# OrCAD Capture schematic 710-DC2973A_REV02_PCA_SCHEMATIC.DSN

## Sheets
1 PAGE 2: size Custom; note: PRIMARY BATTERY SOH MONITOR WITH PRECISION COULOMB COUNTER / PRECISION COULOMB COUNTER
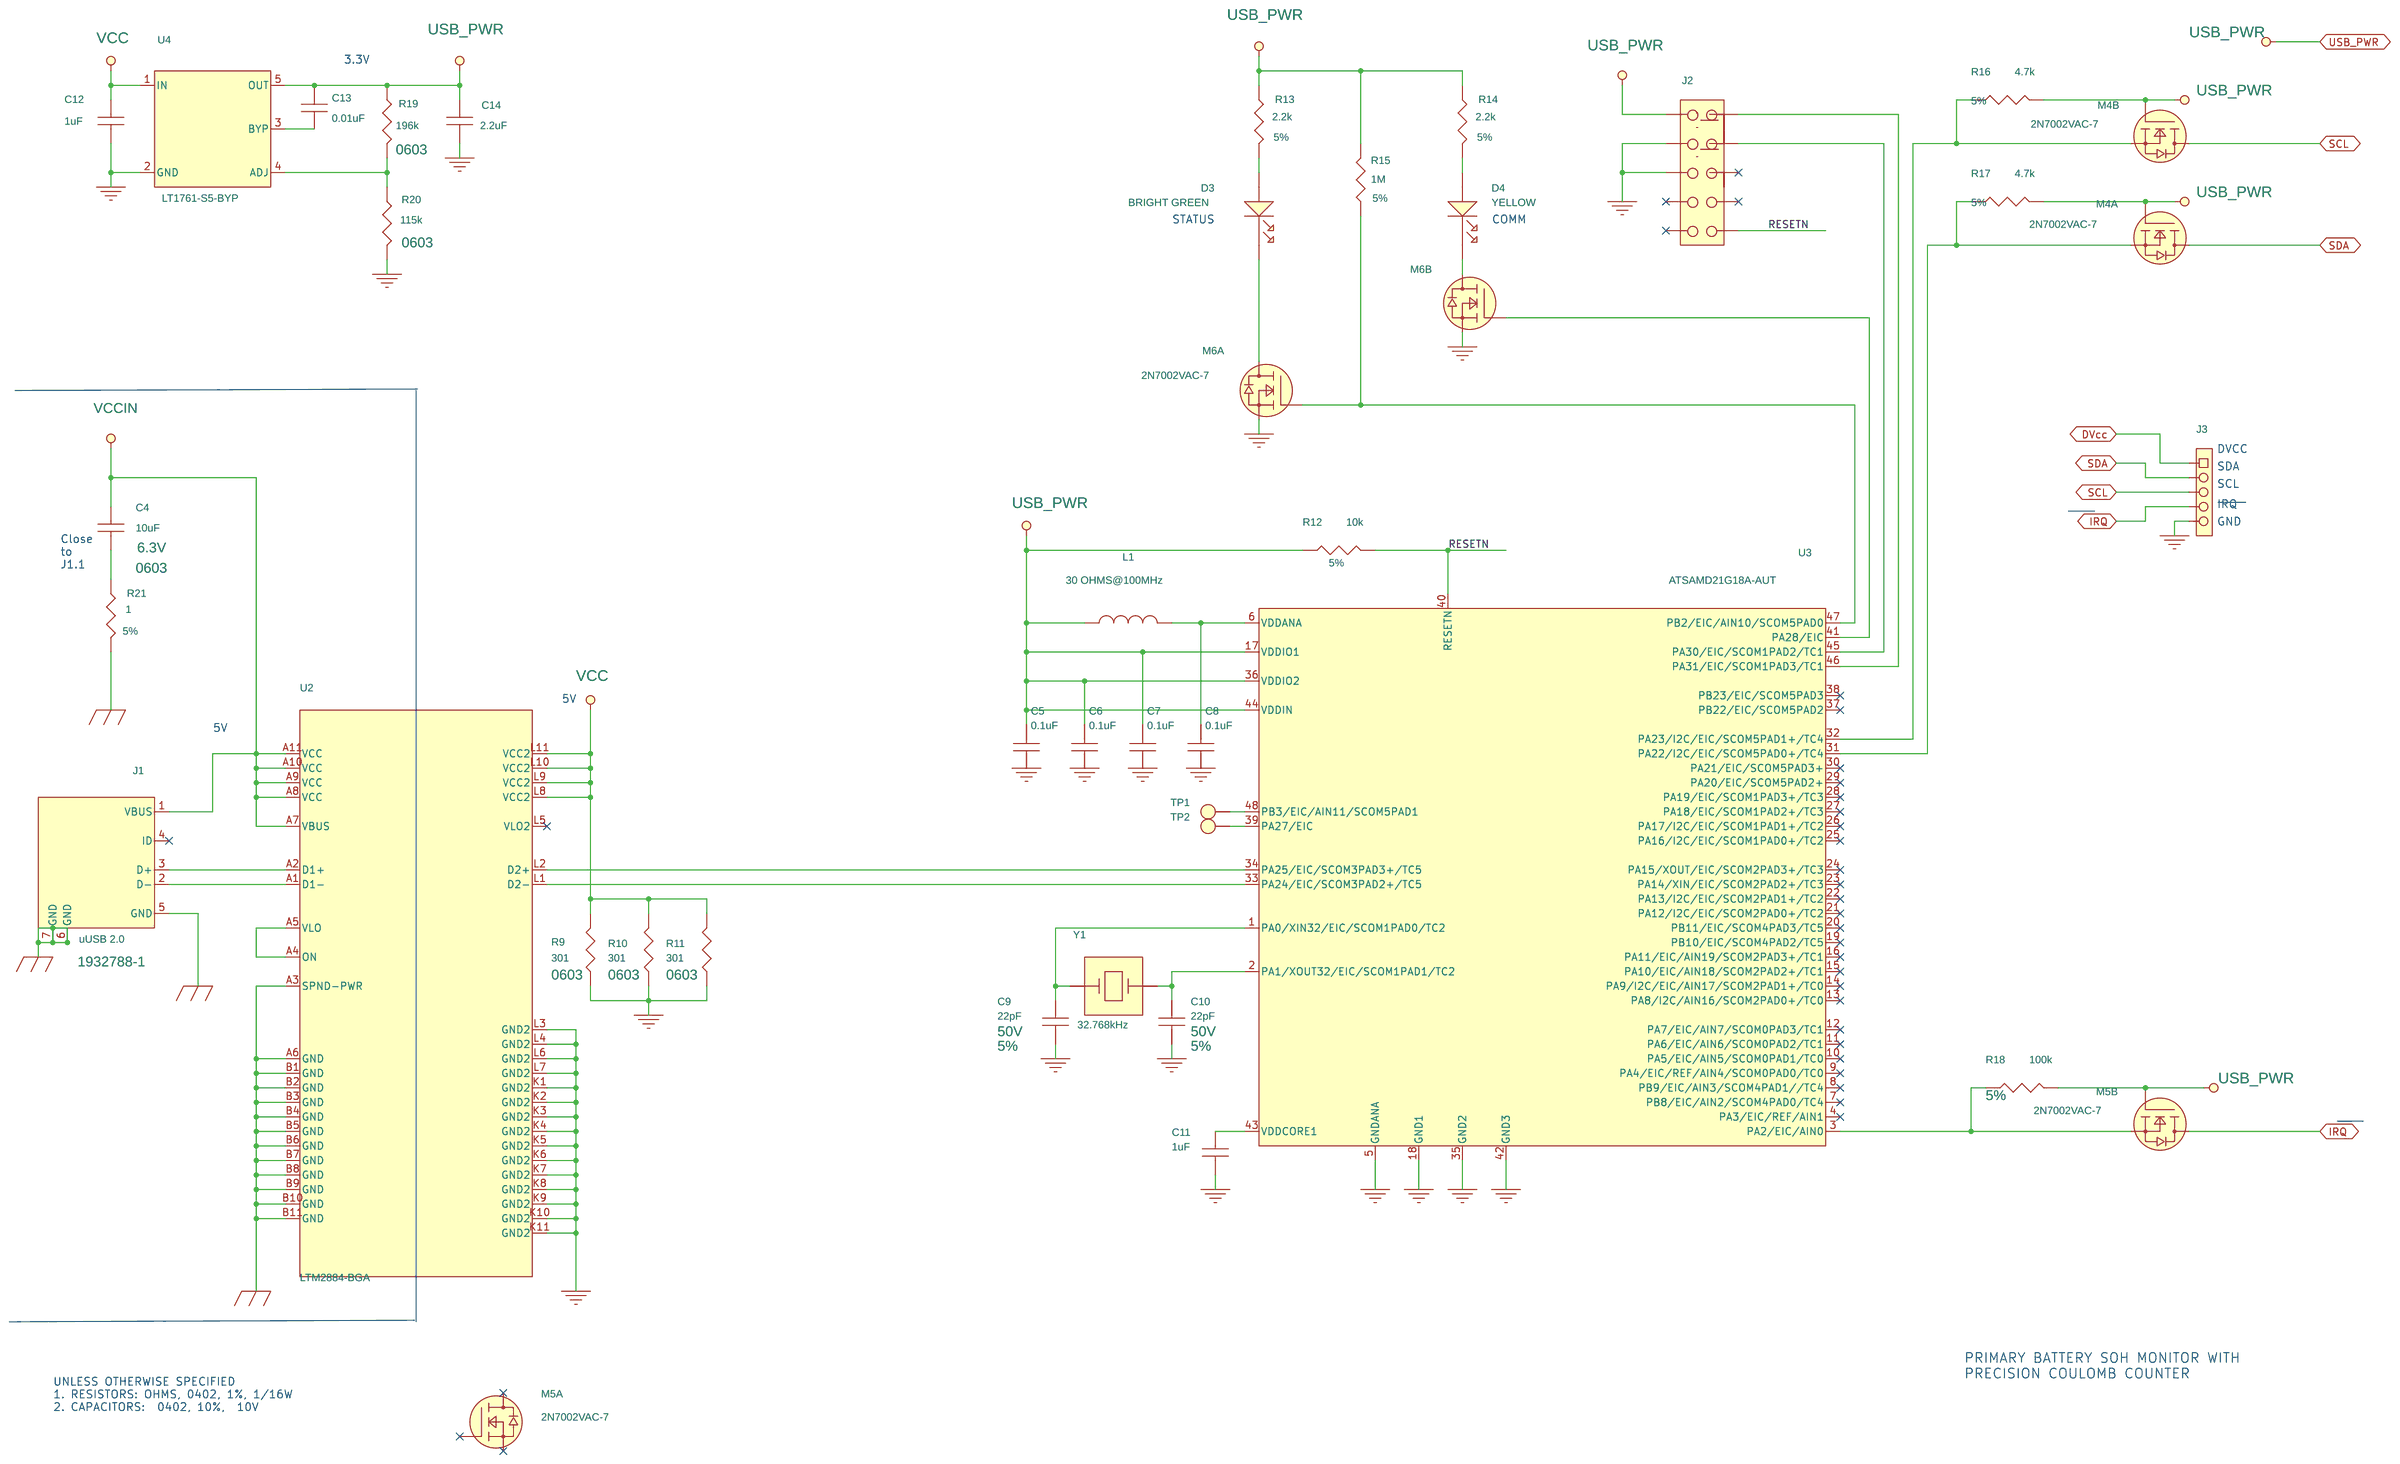
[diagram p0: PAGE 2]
2 PAGE 1: size B
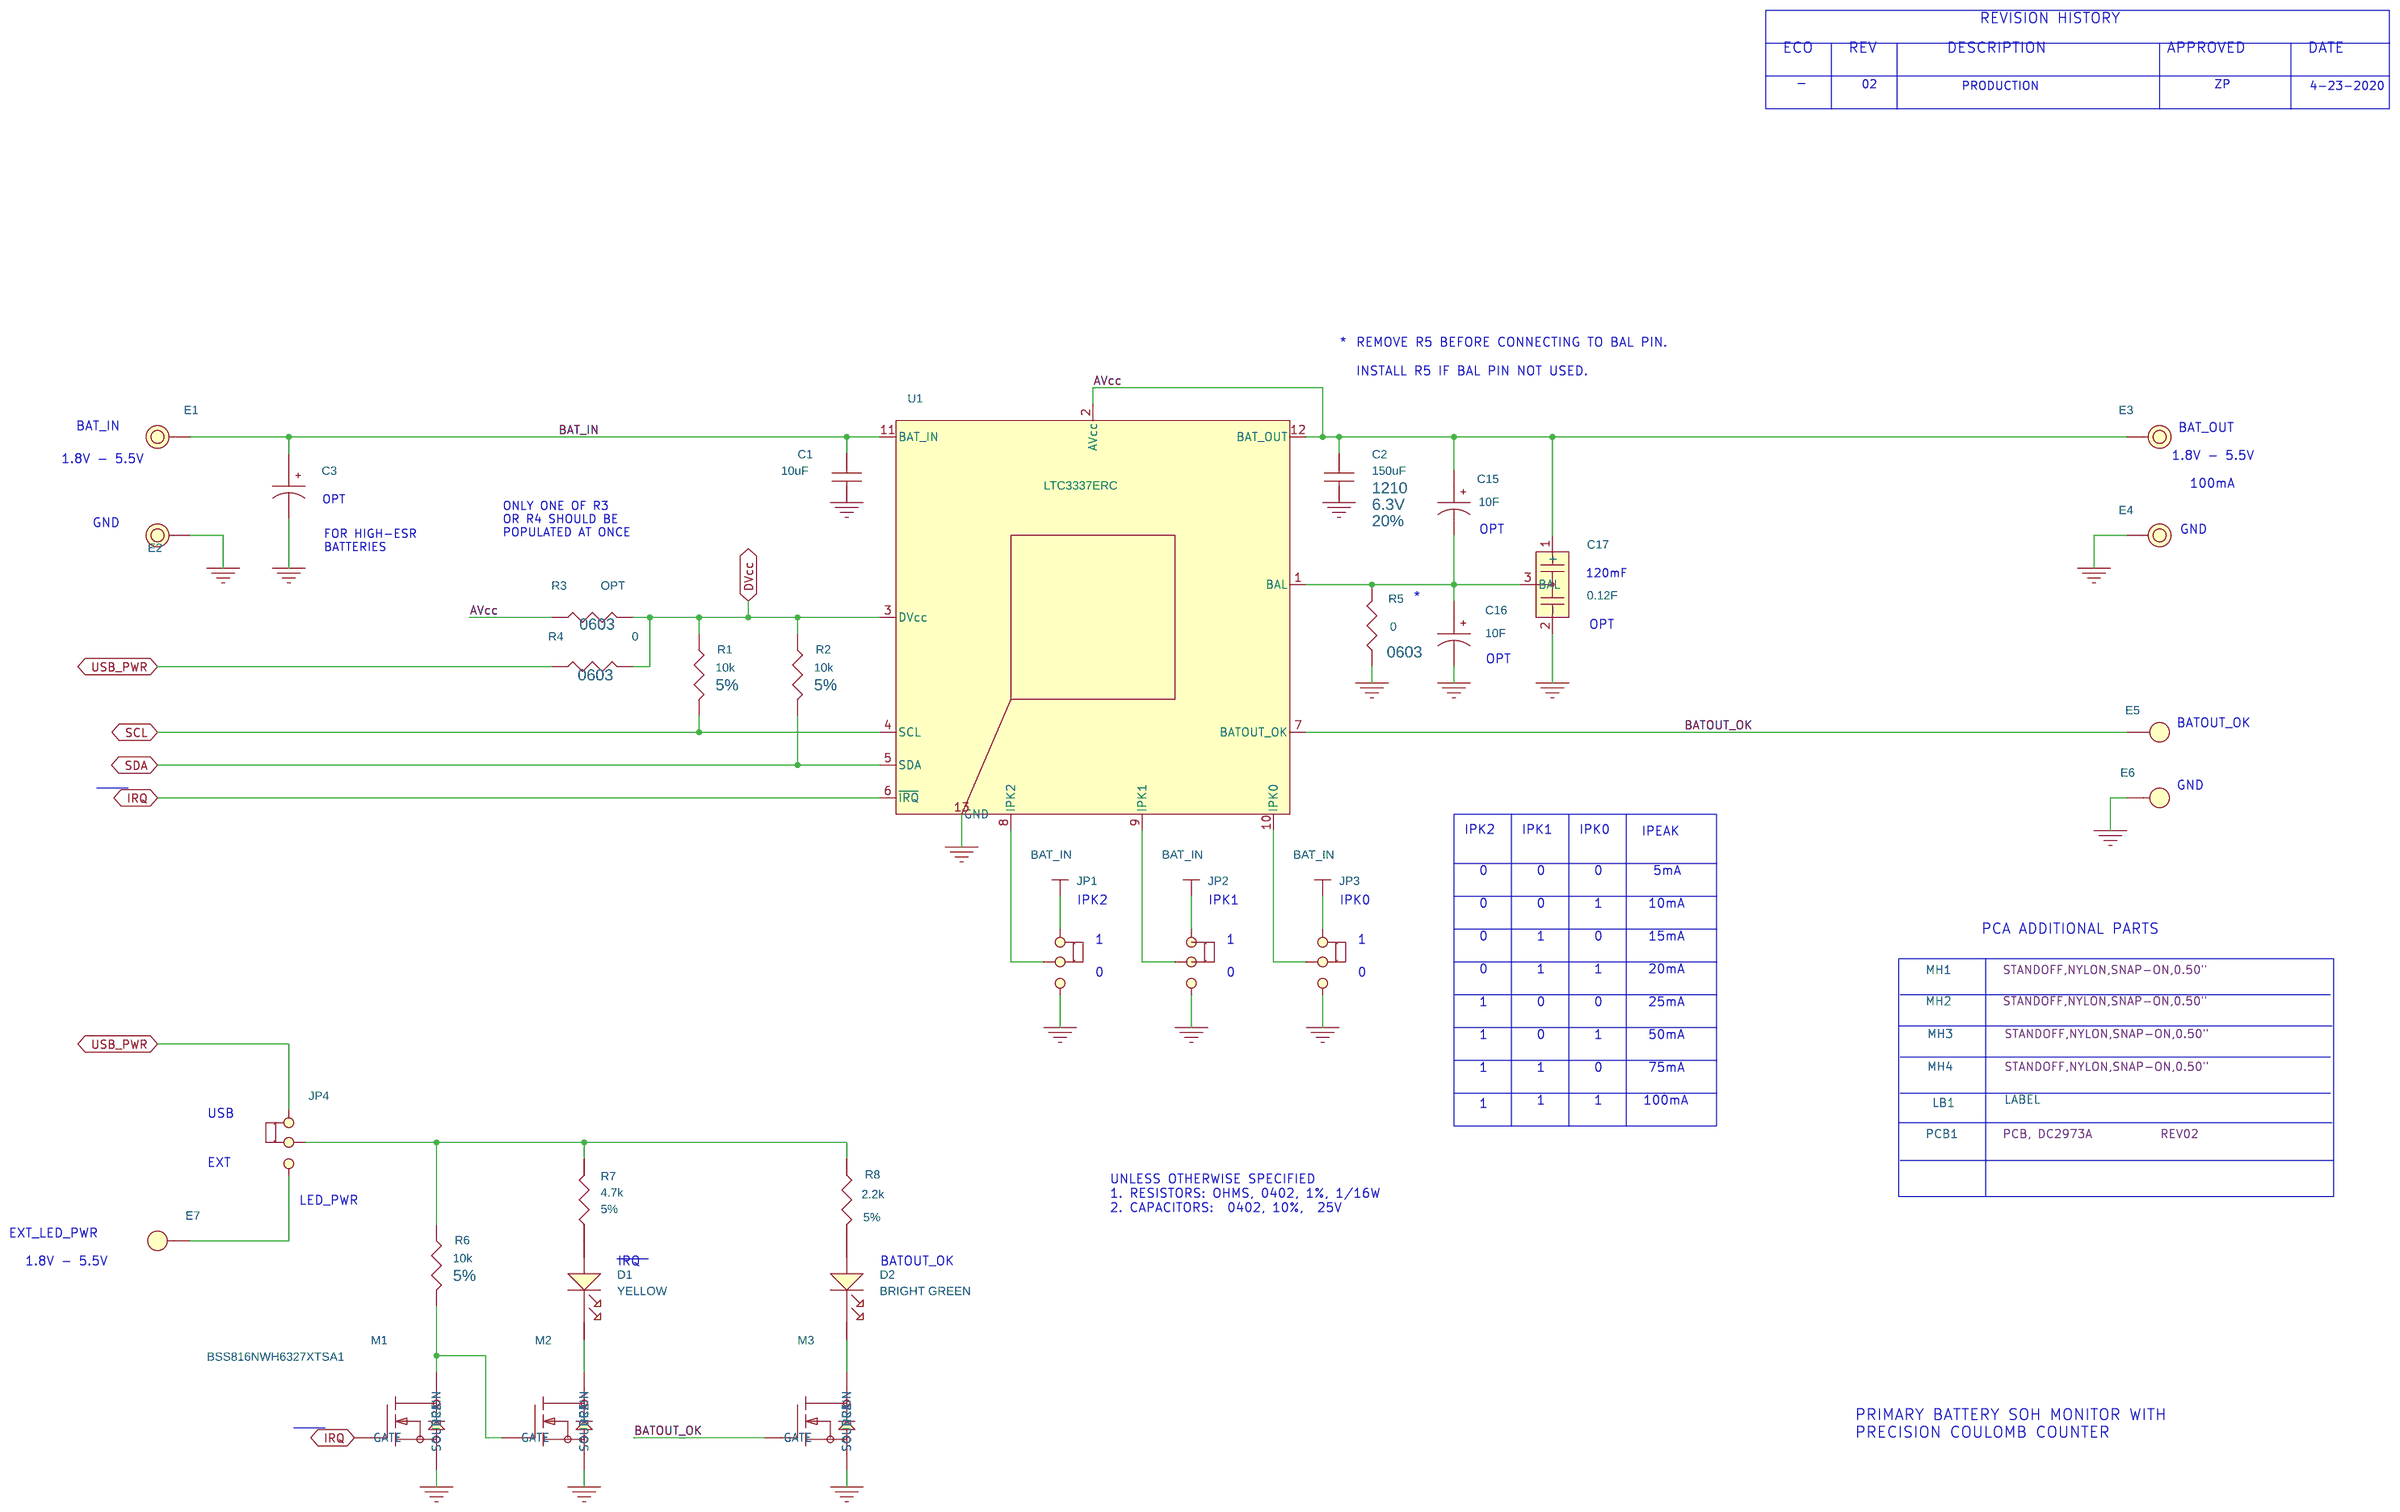
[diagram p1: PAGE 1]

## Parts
sheet PAGE 1
C1  10uF  [CC0603N]
C2  150uF  [CC1210N]
C3  180uF  [PANASONIC_SVPF_8X11.9]
C15  10F  [CAP-ESHSR-0010-0050C0-002R7]
C16  10F  [CAP-ESHSR-0010-0050C0-002R7]
C17  0.12F  [CAP-XX_HA202F]
D1  YELLOW  [LED_0603]
D2  BRIGHT GREEN  [LED_0603]
E1  TEST POINT  [MILLMAX2501]
E2  TEST POINT  [MILLMAX2501]
E3  TEST POINT  [MILLMAX2501]
E4  TEST POINT  [MILLMAX2501]
E5  TEST POINT  [MILLMAX2308]
E6  TEST POINT  [MILLMAX2308]
E7  TEST POINT  [MILLMAX2308]
JP1  HDR  [HD1X3-079]
JP2  HDR  [HD1X3-079]
JP3  HDR  [HD1X3-079]
JP4  HDR  [HD1X3-079]
LB1  LABEL  [895-0154_REV01]
M1  BSS816NWH6327XTSA1  [SOT323-3N]
M2  BSS816NWH6327XTSA1  [SOT323-3N]
M3  BSS816NWH6327XTSA1  [SOT323-3N]
MH1  STANDOFF  [KEYSTONE_8829-8834]
MH2  STANDOFF  [KEYSTONE_8829-8834]
MH3  STANDOFF  [KEYSTONE_8829-8834]
MH4  STANDOFF  [KEYSTONE_8829-8834]
PCB1  PCB, DC2973A
R1  10k  [CR0402N]
R2  10k  [CR0402N]
R3  OPT  [CR0603N]
R4  0  [CR0603N]
R5  0  [CR0603N]
R6  10k  [CR0402N]
R7  4.7k  [CR0402N]
R8  2.2k  [CR0402N]
U1  LTC3337ERC  [LTC-GQFN-12-1784]
XJP1  SHUNT
XJP2  SHUNT
XJP3  SHUNT
XJP4  SHUNT
sheet PAGE 2
C4  10uF  [CC0603N]
C5  0.1uF  [CC0402N]
C6  0.1uF  [CC0402N]
C7  0.1uF  [CC0402N]
C8  0.1uF  [CC0402N]
C9  22pF  [CC0402N]
C10  22pF  [CC0402N]
C11  1uF  [CC0402N]
C12  1uF  [CC0402N]
C13  0.01uF  [CC0402N]
C14  2.2uF  [CC0402N]
D3  BRIGHT GREEN  [LED_0603]
D4  YELLOW  [LED_0603]
J1  uUSB 2.0  [TE-1932788-1]
J2  HDR  [WURTH-62201021121]
J3  HDR  [HD1X5-100]
L1  30 OHMS@100MHz  [IND0805N]
M4  2N7002VAC-7  [SOT563-6N]  (sections A,B)
M5  2N7002VAC-7  [SOT563-6N]  (sections A,B)
M6  2N7002VAC-7  [SOT563-6N]  (sections A,B)
R9  301  [CR0603N]
R10  301  [CR0603N]
R11  301  [CR0603N]
R12  10k  [CR0402N]
R13  2.2k  [CR0402N]
R14  2.2k  [CR0402N]
R15  1M  [CR0402N]
R16  4.7k  [CR0402N]
R17  4.7k  [CR0402N]
R18  100k  [CR0402N]
R19  196k  [CR0603N]
R20  115k  [CR0603N]
R21  1  [CR0402N]
TP1  TEST PAD  [PADSTYLE1]
TP2  TEST PAD  [PADSTYLE1]
U2  LTM2884-BGA  [LTC-BGA-44-1881]
U3  ATSAMD21G18A-AUT  [MICROCHIP-TQFP48-NO_TAB]
U4  LT1761-S5-BYP  [LTC-S5-5-1635]
Y1  32.768kHz  [ECX-31B]

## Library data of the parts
C1 = CAP: CAP.,10uF,X5R,10V,10%,0603; CLASS: DISCRETE; Dielectric Type: X5R; FPLIST: CC0603N,CC0603L,CC0603M; Inventory Qty: 23058; Manufacturer: AVX; Manufacturer PN: 0603ZD106KAT2A; PART_NUMBER: 150-0576; Package Size: 0603; Rated Voltage: 10V; Tolerance: 10%
C2 = CAP: CAP.,150uF,X5R,6.3V,20%,1210; CLASS: DISCRETE; Dielectric Type: X5R; FPLIST: CC1210N,CC1210L,CC1210M; Inventory Qty: 522; Manufacturer: SAMSUNG; Manufacturer PN: CL32A157MQVNNNE; PART_NUMBER: 150-3513; Package Size: 1210; Rated Voltage: 6.3V; Tolerance: 20%
C3 = CAP_P_ALT: CAP.,180uF,ALUM POLY,OS-CON,25V,20%,8x11.9mm,SMD,RADIAL,E12; CLASS: DISCRETE; Dielectric Type: ALUM POLY,OS-CON; Inventory Qty: 4546; Manufacturer: PANASONIC; Manufacturer PN: 25SVPF180M; PART_NUMBER: 150-2329; Package Size: 8x11.9mm,SMD,RADIAL,E12; Rated Voltage: 25V; Tolerance: 20%; UserField01: 16mOhms, 4.65A
C15 C16 = CAP_P_ALT: CAP.,10F,ULTRA,2.7V,-10/+20%,RADIAL,THT; CLASS: DISCRETE; Dielectric Type: ULTRA; Inventory Qty: 472; Manufacturer: NESSCAP CO. LTD.; Manufacturer PN: BCAP0010 P270 S01; PART_NUMBER: 150-0245; Package Size: RADIAL,THT; Rated Voltage: 2.7V; Tolerance: -10/+20%
C17 = CAP-XX-HA202F: CAP.,0.12F,SUPERCAP,HIGH TEMP,5.5V,20%,20mmX18mmX2.5mm,SMD,DUAL CELL; CLASS: DISCRETE; Dielectric Type: SUPERCAP,HIGH TEMP; Inventory Qty: 0; Manufacturer: CAP-XX; Manufacturer PN: HA202F; PART_NUMBER: 150-1825; Package Size: 20mmX18mmX2.5mm,SMD; Package Type: Surface Mount; Rated Voltage: 5.5V; Tolerance: 20%
D1 D4 = LED_ALT: LED,YELLOW,WATERCLEAR,0603; CLASS: DISCRETE; FPLIST: LED_0603N,LED_0603L,LED_0603M; Inventory Qty: 342; Manufacturer: WURTH ELEKTRONIK; Manufacturer PN: 150060YS75000; PART_NUMBER: 270-0136; Package Size: 0603 (1608 Metric); Package Type: 0603
D2 D3 = LED_ALT: LED,BRIGHT GREEN,WATERCLEAR,0603; CLASS: DISCRETE; FPLIST: LED_0603N,LED_0603L,LED_0603M; Inventory Qty: 1970; Manufacturer: WURTH ELEKTRONIK; Manufacturer PN: 150060VS75000; PART_NUMBER: 270-0072; Package Size: 0603 (1608 Metric); Package Type: 0603
E1-E4 = TESTPOINT_.219_MILL-MAX_2501: TEST POINT,TURRET,0.094" MTG. HOLE,PCB 0.062" THK; CLASS: IO; Inventory Qty: 609555; Manufacturer: MILL-MAX; Manufacturer PN: 2501-2-00-80-00-00-07-0; PART_NUMBER: 260-0003
E5-E7 = TEST_POINT_.156_MILL-MAX_2308: TEST POINT,TURRET,0.064" MTG. HOLE,PCB 0.062" THK; CLASS: IO; Inventory Qty: 907628; Manufacturer: MILL-MAX; Manufacturer PN: 2308-2-00-80-00-00-07-0; PART_NUMBER: 260-0004
JP1-JP4 = HDR3X1_A: CONN.,HDR,MALE,1x3,2mm,VERT,ST,THT,10u" Au; CLASS: IO; Inventory Qty: 44806; Manufacturer: SAMTEC; Manufacturer PN: TMM-103-02-L-S; PART_NUMBER: 250-0422
LB1 = BLANK_LABEL: LABEL SPEC, DEMO BOARD SERIAL NUMBER; Inventory Qty: 0; Manufacturer: BRADY; Manufacturer PN: THT-96-717-10; PART_NUMBER: 895-0154
M1-M3 = NMOS_SOT: XSTR.,MOSFET, N-CH,20V,1.4A,SOT-323,AEC-Q200; CLASS: DISCRETE; FPLIST: SOT323-3N,SOT323-3L,SOT323-3M; Inventory Qty: 5950; Manufacturer: INFINEON; PART_NUMBER: 240-0375; Package Size: SC-70, SOT-323; Package Type: SOT-323; Polarity: N-Channel; Rated Voltage: 20V
MH1-MH4 = BLANK_MECHANICAL_PART: STANDOFF,NYLON,SNAP-ON,0.50"; CLASS: DISCRETE; Inventory Qty: 197874; Manufacturer: KEYSTONE; Manufacturer PN: 8833; PART_NUMBER: 763-0007
PCB1 = BLANK_PCB_PART: BOM Notes: REV02; CLASS: DISCRETE; Inventory Qty: 0; Manufacturer: ADI APPROVED SUPPLIER; Manufacturer PN: 600-DC2973A; PART_NUMBER: 600-DC2973A
R1 R2 R6 = RES: RES.,10k OHMS,5%,1/16W,0402,AEC-Q200; CLASS: DISCRETE; FPLIST: CR0402N,CR0402L,CR0402M; Inventory Qty: 69667; Manufacturer: NIC; Manufacturer PN: NRC04J103TRF; PART_NUMBER: 100-0214; Package Size: 0402; Rated Power: 1/16W; Temperature Coefficient: 200ppm; Tolerance: 5%
R3 = RES: RES., OPTION, 0603; CLASS: DISCRETE; FPLIST: CR0603N,CR0603L,CR0603M; PART_NUMBER: 100-2374; Package Size: 0603
R4 R5 = RES: RES.,0 OHM,1%,0603,AEC-Q200; CLASS: DISCRETE; FPLIST: CR0603N,CR0603L,CR0603M; Inventory Qty: 34533; Manufacturer: KOA SPEER; Manufacturer PN: RK73Z1JTTDD; PART_NUMBER: 100-0596; Package Size: 0603; Tolerance: 1%
R7 R16 R17 = RES: RES.,4.7k OHMS,5%,1/16W,0402,AEC-Q200; CLASS: DISCRETE; FPLIST: CR0402N,CR0402L,CR0402M; Inventory Qty: 31964; Manufacturer: NIC; Manufacturer PN: NRC04J472TRF; PART_NUMBER: 100-0216; Package Size: 0402; Rated Power: 1/16W; Temperature Coefficient: 200ppm; Tolerance: 5%
R8 R13 R14 = RES: RES.,2.2k OHMS,5%,1/16W,0402,AEC-Q200; CLASS: DISCRETE; FPLIST: CR0402N,CR0402L,CR0402M; Inventory Qty: 57911; Manufacturer: VISHAY; Manufacturer PN: CRCW04022K20JNED; PART_NUMBER: 100-0324; Package Size: 0402; Rated Power: 1/16W; Temperature Coefficient: 200ppm; Tolerance: 5%
U1 = LTC3337-GQFN: Primary Battery SOH Monitor w/ Precision Coulomb Counter,GQFN-12; CLASS: IC; Inventory Qty: 0; Manufacturer: ANALOG DEVICES; Manufacturer PN: LTC3337ERC#PBF; PART_NUMBER: LTC3337ERC#PBF; Package Size: 12-GQFN; Package Type: GQFN-12
XJP1-XJP4 = CONN_SHUNT_2_POS_2mm: CONN.,SHUNT,FEMALE,2 POS,2mm; CLASS: IO; Inventory Qty: 67675; Manufacturer: Wurth Elektronik; Manufacturer PN: 60800213421; PART_NUMBER: 250-0485
C4 = CAP: CAP.,10uF,X5R,6.3V,20%,0603; CLASS: DISCRETE; Dielectric Type: X5R; Inventory Qty: 62711; Manufacturer: MURATA; Manufacturer PN: GRM188R60J106ME47D; PART_NUMBER: 150-3401; Package Size: 0603; Package Type: SMD; Rated Voltage: 6.3V; Tolerance: 20%
C5-C8 = CAP: CAP.,0.1uF,X5R,10V,20%,0402; CLASS: DISCRETE; Dielectric Type: X5R; Inventory Qty: 3880; Manufacturer: WURTH ELEKTRONIK; Manufacturer PN: 885012105010; PART_NUMBER: 150-2539; Package Size: 0402; Package Type: SMD; Rated Voltage: 10V; SIGNAL_MODEL: DEFAULT_CAPACITOR_100000pF_1_2; Temperature Coefficient: X5R; Tolerance: 20%
C9 C10 = CAP: CAP.,22pF,NP0,50V,5%,0402; CLASS: DISCRETE; Dielectric Type: NP0; Inventory Qty: 1440; Manufacturer: WURTH ELEKTRONIK; Manufacturer PN: 885012005057; PART_NUMBER: 150-2540; Package Size: 0402; Package Type: SMD; Rated Voltage: 50V; SIGNAL_MODEL: DEFAULT_CAPACITOR_22.000000pF_1_2; Temperature Coefficient: C0G, NP0; Tolerance: 5%
C11 C12 = CAP: CAP.,1uF,BJ,10V,20%,0402; CLASS: DISCRETE; Dielectric Type: BJ; FPLIST: CC0402N, CC0402M,CC0402L; Inventory Qty: 12000; Manufacturer: TDK; Manufacturer PN: CGB2A1JB1A105M033BC; PART_NUMBER: 150-2558; Package Size: 0402; Package Type: Surface Mount, MLCC; Rated Voltage: 10V; SIGNAL_MODEL: DEFAULT_CAPACITOR_1e+06pF_1_2; Temperature Coefficient: JB; Tolerance: 20%
C13 = CAP: CAP.,0.01uF,X7R,25V,10%,0402; CLASS: DISCRETE; Dielectric Type: X7R; Inventory Qty: 1470; Manufacturer: WURTH ELEKTRONIK; Manufacturer PN: 885012205050; PART_NUMBER: 150-2542; Package Size: 0402; Package Type: SMD; Rated Voltage: 25V; SIGNAL_MODEL: DEFAULT_CAPACITOR_10000pF_1_2; Temperature Coefficient: X7R; Tolerance: 10%
C14 = CAP: CAP.,2.2uF,X5R,10V,20%,0402; CLASS: DISCRETE; Dielectric Type: X5R; Inventory Qty: 1970; Manufacturer: WURTH ELEKTRONIK; Manufacturer PN: 885012105013; PART_NUMBER: 150-2543; Package Size: 0402; Package Type: SMD; Rated Voltage: 10V; SIGNAL_MODEL: DEFAULT_CAPACITOR_2.2e+06pF_1_2; Temperature Coefficient: X5R; Tolerance: 20%
J1 = MICRO_USB_2.0: CONN.,uUSB 2.0,RCPT.,5-PIN,1PORT,REVERSE MOUNT,R/A HORZ.,TYPE B, FLANGELESS; CLASS: IO; Inventory Qty: 3957; Manufacturer: TE CONNECTIVITY; Manufacturer PN: 1932788-1; PART_NUMBER: 250-0536
J2 = HEADER_2X5_.100: CONN.,HDR,MALE,2x5,1.27mm,VERT,ST,THT; CLASS: IO; Inventory Qty: 6170; Manufacturer: WURTH ELEKTRONIK; Manufacturer PN: 62201021121; PART_NUMBER: 250-0763
J3 = HEADER_1X5: CONN.,HDR,MALE,1x5,2.54mm,VERT,ST,THT; CLASS: IO; Inventory Qty: 10760; Manufacturer: SAMTEC; Manufacturer PN: TSW-105-07-L-S; PART_NUMBER: 250-0599; Package Size: 0.230" (5.84mm)
L1 = FERRITEBEAD: IND.,30 OHMS@100MHz,BEAD,10%,6A,10mOHMS,0805,1LN; CLASS: DISCRETE; Inventory Qty: 11475; Manufacturer: TDK; Manufacturer PN: MPZ2012S300AT000; PART_NUMBER: 200-0237; Package Size: 0805; Tolerance: 10%
M4-M6 = 2N7002VAC-7: XSTR.,MOSFET,DUAL,N-CH,280mA,SOT-563; CLASS: DISCRETE; Inventory Qty: 8986; Manufacturer: DIODES INC.; PART_NUMBER: 240-0199; Package Size: SOT-563, SOT-666; Package Type: SOT-563; Polarity: 2 N-Channel (Dual); Rated Power: 150mW; Rated Voltage: 60V
R9-R11 = RES: RES.,301 OHMS,1%,1/10W,0603,AEC-Q200; CLASS: DISCRETE; Inventory Qty: 38848; Manufacturer: PANASONIC; Manufacturer PN: ERJ3EKF3010V; PART_NUMBER: 100-0434; Package Size: 0603; Rated Power: 1/10W; Temperature Coefficient: 100ppm; Tolerance: 1%
R12 = RES: RES.,10k OHMS,5%,1/16W,0402; CLASS: DISCRETE; FPLIST: CR0402N,CR0402L,CR0402M; Inventory Qty: 77544; Manufacturer: SAMSUNG; Manufacturer PN: RC1005J103CS; PART_NUMBER: 100-0023; Package Size: 0402; Rated Power: 1/16W; SIGNAL_MODEL: DEFAULT_RESISTOR_10000OHM_1_2; Temperature Coefficient: +/-100ppm; Tolerance: 5%
R15 = RES: RES.,1M OHM,5%,1/16W,0402,AEC-Q200; CLASS: DISCRETE; FPLIST: CR0402N,CR0402L,CR0402M; Inventory Qty: 26140; Manufacturer: VISHAY; Manufacturer PN: CRCW04021M00JNED; PART_NUMBER: 100-0321; Package Size: 0402; Rated Power: 1/16W; SIGNAL_MODEL: DEFAULT_RESISTOR_0.001OHM_1_2; Temperature Coefficient: 200ppm; Tolerance: 5%
R18 = RES: RES.,100k OHMS,5%,1/16W,0402,AEC-Q200; CLASS: DISCRETE; FPLIST: CR0402N,CR0402L,CR0402M; Inventory Qty: 0; Manufacturer: ROHM; Manufacturer PN: MCR01MZPJ104; PART_NUMBER: 100-0192; Package Size: 0402; Rated Power: 1/16W; Temperature Coefficient: 200ppm/C; Tolerance: 5%
R19 = RES: RES.,196k OHMS,1%,1/10W,0603; CLASS: DISCRETE; FPLIST: CR0603N,CR0603L,CR0603M; Inventory Qty: 23006; Manufacturer: VISHAY; Manufacturer PN: CRCW0603196KFKEA; PART_NUMBER: 100-2660; Package Size: 0603; Rated Power: 1/10W; Temperature Coefficient: 100ppm/C; Tolerance: 1%
R20 = RES: RES.,115k OHMS,1%,1/10W,0603; CLASS: DISCRETE; FPLIST: CR0603N,CR0603L,CR0603M; Inventory Qty: 22818; Manufacturer: NIC; Manufacturer PN: NRC06F1153TRF; PART_NUMBER: 100-2580; Package Size: 0603; Rated Power: 1/10W; Temperature Coefficient: 100ppm; Tolerance: 1%
R21 = RES: RES.,1 OHM,5%,1/16W,0402,AEC-Q200; CLASS: DISCRETE; FPLIST: CR0402N,CR0402L,CR0402M; Inventory Qty: 29204; Manufacturer: KOA SPEER; Manufacturer PN: RK73B1ETTP1R0J; PART_NUMBER: 100-0208; Package Size: 0402; Rated Power: 1/16W; Temperature Coefficient: +/-200ppm; Tolerance: 5%
TP1 TP2 = PAD_STYLE_E: TESTPOINT, PCB COPPER FEATURE; CLASS: IO; FPLIST: PADSTYLE1,PADSTYLE2,PADSTYLE3,PADSTYLE4,PADSTYLE5,PADSTYLE6,PADSTYLE7,PADSTYLE8; PART_NUMBER: PCBPADS-8
U2 = LTM2884-BGA: IC,USB 2.0 uModuleTransceiver,BGA-44; CLASS: IC; Inventory Qty: 233; Manufacturer: LINEAR TECH.; Manufacturer PN: LTM2884CY#PBF; PART_NUMBER: LTM2884CY#PBF; Package Type: BGA-44
U3 = ATSAMD21G18A-AUT: IC, MEMORY,MCU,32BIT, 256KB FLASH,TQFP48; CLASS: IC; FPLIST: MICROCHIP-TQFP48,MICROCHIP-TQFP48-NO_TAB; Inventory Qty: 3270; Manufacturer: MICROCHIP; PART_NUMBER: 380-0098; Package Size: 48-TQFP; Package Type: TQFP48; Supply Voltage: 1.62 V - 3.6 V
U4 = LT1761-S5-BYP_ALT1: IC,REG LDO ADJ, 100mA,TSOT23-5; CLASS: IC; Inventory Qty: 120; Manufacturer: LINEAR TECH.; Manufacturer PN: LT1761ES5-BYP#PBF; PART_NUMBER: LT1761ES5-BYP#PBF; Package Size: TSOT-23; Package Type: TSOT23-5
Y1 = XTAL_B: CRYSTAL,32.768kHz,12.5pF,3.2x1.5mm SMD; CLASS: DISCRETE; Frequency Tolerance: 20ppm; Inventory Qty: 60524; Manufacturer: ABRACON; Manufacturer PN: ABS07-32.768kHz-4-T; PART_NUMBER: 340-0066; Package Size: 0.126" L x 0.059" W (3.20mm x 1.50mm)

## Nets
AVcc: C2.1 C15.1 C17.1(+) E3.1 R3.1 U1.2(AVcc) U1.12(BAT_OUT)
DVcc: J3.1 R1.1 R2.1 R3.2 R4.2 U1.3(DVcc)
GND: C1.2 C2.2 C3.2 C5.1 C6.1 C7.1 C8.1 C9.2 C10.2 C11.2 C12.2 C14.2 C16.2 C17.2(-) E2.1 E4.1 E6.1(A) J2.3 J2.5 J3.5 JP1.3 JP2.3 JP3.3 M1.2(SOURCE) M2.2(SOURCE) M3.2(SOURCE) M6.2(S) M6.5(S) R5.1 R9.1 R10.1 R11.1 R20.2 U1.13(GND) U2.K1(GND2) U2.K2(GND2) U2.K3(GND2) U2.K4(GND2) U2.K5(GND2) U2.K6(GND2) U2.K7(GND2) U2.K8(GND2) U2.K9(GND2) U2.K10(GND2) U2.K11(GND2) U2.L3(GND2) U2.L4(GND2) U2.L6(GND2) U2.L7(GND2) U3.5(GNDANA) U3.18(GND1) U3.35(GND2) U3.42(GND3) U4.2(GND)
GND_EARTH: J1.5(GND) J1.6(GND) J1.7(GND) R21.2 U2.A3(SPND-PWR) U2.A6(GND) U2.B1(GND) U2.B2(GND) U2.B3(GND) U2.B4(GND) U2.B5(GND) U2.B6(GND) U2.B7(GND) U2.B8(GND) U2.B9(GND) U2.B10(GND) U2.B11(GND)
Vcc: C12.1 R9.2 R10.2 R11.2 U2.L8(VCC2) U2.L9(VCC2) U2.L10(VCC2) U2.L11(VCC2) U4.1(IN)
VCCin: C4.1 J1.1(VBUS) U2.A7(VBUS) U2.A8(VCC) U2.A9(VCC) U2.A10(VCC) U2.A11(VCC)
BAT_IN: C1.1 C3.1 E1.1 JP1.1 JP2.1 JP3.1 U1.11(BAT_IN)
BATOUT_OK: E5.1(A) M3.1(GATE) U1.7(BATOUT_OK)
IRQ: J3.4 M1.1(GATE) M5.3(D) U1.6(~{IRQ})
RESETN: J2.10 R12.1 U3.40(RESETN)
SCL: J3.3 M4.3(D) R1.2 U1.4(SCL)
SDA: J3.2 M4.6(D) R2.2 U1.5(SDA)
USB_PWR: C5.2 C6.2 C7.2 C13.2 C14.1 J2.1 JP4.1 L1.1 M4.1(G) M4.4(G) M5.4(G) R4.1 R12.2 R13.1 R14.1 R15.2 R16.2 R17.2 R18.2 R19.1 U3.17(VDDIO1) U3.36(VDDIO2) U3.44(VDDIN) U4.5(OUT)
N17100315: U2.A4(ON) U2.A5(VLO)
N17100321: C4.2 R21.1
N17100323: J1.2(D-) U2.A1(D1-)
N17100355: J1.3(D+) U2.A2(D1+)
N17100949: U2.L1(D2-) U3.33(PA24/EIC/SCOM3PAD2+/TC5)
N17100951: U2.L2(D2+) U3.34(PA25/EIC/SCOM3PAD3+/TC5)
N17252381: C8.2 L1.2 U3.6(VDDANA)
N17252406: M6.1(G) R15.1 U3.47(PB2/EIC/AIN10/SCOM5PAD0)
N17252432: M4.5(S) R16.1 U3.32(PA23/I2C/EIC/SCOM5PAD1+/TC4)
N17252439: M4.2(S) R17.1 U3.31(PA22/I2C/EIC/SCOM5PAD0+/TC4)
N17252441: D4.2(ANODE) R14.2
N17252443: D3.2(ANODE) R13.2
N17252445: D4.1(CATHODE) M6.3(D)
N17252447: D3.1(CATHODE) M6.6(D)
N17252461: M6.4(G) U3.41(PA28/EIC)
N17252463: M5.5(S) R18.1 U3.3(PA2/EIC/AIN0)
N17252598: J2.4 U3.45(PA30/EIC/SCOM1PAD2/TC1)
N17252686: C11.1 U3.43(VDDCORE1)
N17252778: C10.1 U3.2(PA1/XOUT32/EIC/SCOM1PAD1/TC2) Y1.2
N17252780: C9.1 U3.1(PA0/XIN32/EIC/SCOM1PAD0/TC2) Y1.1
N17252790: J2.2 U3.46(PA31/EIC/SCOM1PAD3/TC1)
N17258071: R19.2 R20.1 U4.4(ADJ)
N17258103: C13.1 U4.3(BYP)
N17370826: C15.2 C16.1 C17.3(BAL) R5.2 U1.1(BAL)
N17374573: JP1.2 U1.8(IPK2)
N17374972: JP2.2 U1.9(IPK1)
N17374986: JP3.2 U1.10(IPK0)
N17382611: E7.1(A) JP4.3
N17382642: JP4.2 R6.1 R7.2 R8.1
N17389449: M1.3(DRAIN) M2.1(GATE) R6.2
N17389513: D1.1(CATHODE) M2.3(DRAIN)
N17390120: D2.1(CATHODE) M3.3(DRAIN)
N17393464: TP1.1(TP) U3.48(PB3/EIC/AIN11/SCOM5PAD1)
N17393480: TP2.1(TP) U3.39(PA27/EIC)
N17429433: D2.2(ANODE) R8.2
N17429435: D1.2(ANODE) R7.1

Not connected (* = marked no-connect by the designer): J1 4(ID)*; J2 6* 7* 8* 9*; M5 1(G)* 2(S)* 6(D)*; U2 L5(VLO2)*; U3 4(PA3/EIC/REF/AIN1)* 7(PB8/EIC/AIN2/SCOM4PAD0/TC4)* 8(PB9/EIC/AIN3/SCOM4PAD1//TC4)* 9(PA4/EIC/REF/AIN4/SCOM0PAD0/TC0)* 10(PA5/EIC/AIN5/SCOM0PAD1/TC0)* 11(PA6/EIC/AIN6/SCOM0PAD2/TC1)* 12(PA7/EIC/AIN7/SCOM0PAD3/TC1)* 13(PA8/I2C/AIN16/SCOM2PAD0+/TC0)* 14(PA9/I2C/EIC/AIN17/SCOM2PAD1+/TC0)* 15(PA10/EIC/AIN18/SCOM2PAD2+/TC1)* 16(PA11/EIC/AIN19/SCOM2PAD3+/TC1)* 19(PB10/EIC/SCOM4PAD2/TC5)* 20(PB11/EIC/SCOM4PAD3/TC5)* 21(PA12/I2C/EIC/SCOM2PAD0+/TC2)* 22(PA13/I2C/EIC/SCOM2PAD1+/TC2)* 23(PA14/XIN/EIC/SCOM2PAD2+/TC3)* 24(PA15/XOUT/EIC/SCOM2PAD3+/TC3)* 25(PA16/I2C/EIC/SCOM1PAD0+/TC2)* 26(PA17/I2C/EIC/SCOM1PAD1+/TC2)* 27(PA18/EIC/SCOM1PAD2+/TC3)* 28(PA19/EIC/SCOM1PAD3+/TC3)* 29(PA20/EIC/SCOM5PAD2+)* 30(PA21/EIC/SCOM5PAD3+)* 37(PB22/EIC/SCOM5PAD2)* 38(PB23/EIC/SCOM5PAD3)*

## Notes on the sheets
sheet 1
- 3.3V
- STATUS
- COMM
- DVCC
- SDA
- SCL
- IRQ
- GND
- Close
  to
  J1.1
- 5V
- 5V
- PRIMARY BATTERY SOH MONITOR WITH
  PRECISION COULOMB COUNTER
- UNLESS OTHERWISE SPECIFIED
  1. RESISTORS: OHMS, 0402, 1%, 1/16W
  2. CAPACITORS:  0402, 10%,  10V
sheet 2
- REVISION HISTORY
- ECO
- REV
- DESCRIPTION
- APPROVED
- DATE
- -
- 02
- PRODUCTION
- ZP
- 4-23-2020
- *
- REMOVE R5 BEFORE CONNECTING TO BAL PIN.
  INSTALL R5 IF BAL PIN NOT USED.
- BAT_IN
- BAT_OUT
- 1.8V - 5.5V
- 1.8V - 5.5V
- 100mA
- OPT
- ONLY ONE OF R3
  OR R4 SHOULD BE
  POPULATED AT ONCE
- GND
- FOR HIGH-ESR
  BATTERIES
- OPT
- GND
- 120mF
- *
- OPT
- OPT
- BATOUT_OK
- GND
- IPK2
- IPK1
- IPK0
- IPEAK
- 0
- 0
- 0
- 5mA
- IPK2
- IPK1
- IPK0
- 0
- 0
- 1
- 10mA
- PCA ADDITIONAL PARTS
- 1
- 1
- 1
- 0
- 1
- 0
- 15mA
- 0
- 1
- 1
- 20mA
- 0
- 0
- 0
- 1
- 0
- 0
- 25mA
- 1
- 0
- 1
- 50mA
- 1
- 1
- 0
- 75mA
- 1
- 1
- 1
- 100mA
- USB
- EXT
- UNLESS OTHERWISE SPECIFIED
  1. RESISTORS: OHMS, 0402, 1%, 1/16W
  2. CAPACITORS:  0402, 10%,  25V
- LED_PWR
- EXT_LED_PWR
- 1.8V - 5.5V
- IRQ
- BATOUT_OK
- PRIMARY BATTERY SOH MONITOR WITH
  PRECISION COULOMB COUNTER
